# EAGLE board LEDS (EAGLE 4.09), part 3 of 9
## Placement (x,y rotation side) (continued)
LED19.97  LED_CROSS1/2  [LED_603]  60.1,4.28 180 top
LED19.98  LED_CROSS1/2  [LED_603]  61.89,4.28 180 top
LED19.99  LED_CROSS1/2  [LED_603]  63.68,4.28 180 top
LED19.100  LED_CROSS1/2  [LED_603]  65.49,4.28 180 top
LED19.101  LED_CROSS1/2  [LED_603]  67.18,4.32 180 top
LED19.102  LED_CROSS1/2  [LED_603]  68.95,4.32 180 top
LED19.103  LED_CROSS1/2  [LED_603]  70.7,4.32 180 top
LED19.104  LED_CROSS1/2  [LED_603]  72.45,4.32 180 top
LED19.105  LED_CROSS1/2  [LED_603]  74.2,4.32 180 top
LED19.106  LED_CROSS1/2  [LED_603]  75.95,4.32 180 top
LED19.107  LED_CROSS1/2  [LED_603]  77.73,4.32 180 top
LED19.108  LED_CROSS1/2  [LED_603]  79.48,4.32 180 top
LED19.109  LED_CROSS1/2  [LED_603]  81.23,4.32 180 top
LED19.110  LED_CROSS1/2  [LED_603]  83.21,4.32 180 top
LED19.111  LED_CROSS1/2  [LED_603]  85.11,4.32 180 top
LED19.112  LED_CROSS1/2  [LED_603]  86.78,4.32 180 top
LED19.113  LED_CROSS1/2  [LED_603]  88.65,4.32 180 top
LED19.114  LED_CROSS1/2  [LED_603]  90.28,4.32 180 top
LED19.115  LED_CROSS1/2  [LED_603]  92,4.32 180 top
LED19.116  LED_CROSS1/2  [LED_603]  93.8,4.32 180 top
LED19.117  LED_CROSS1/2  [LED_603]  95.45,4.32 180 top
LED19.118  LED_CROSS1/2  [LED_603]  97.25,4.32 180 top
LED19.119  LED_CROSS1/2  [LED_603]  99,4.32 180 top
LED19.120  LED_CROSS1/2  [LED_603]  100.73,4.32 180 top
LED19.121  LED_CROSS1/2  [LED_603]  102.5,4.32 180 top
LED19.122  LED_CROSS1/2  [LED_603]  104.2,4.32 180 top
LED19.123  LED_CROSS1/2  [LED_603]  106,4.32 180 top
LED19.124  LED_CROSS1/2  [LED_603]  107.68,4.32 180 top
LED19.125  LED_CROSS1/2  [LED_603]  109.3,4.32 180 top
LED19.126  LED_CROSS1/2  [LED_603]  111.23,4.32 180 top
LED19.127  LED_CROSS1/2  [LED_603]  112.8,4.32 180 top
LED20.0  LED_CROSS1/2  [LED_603]  2.57,30.59 180 top
LED20.1  LED_CROSS1/2  [LED_603]  4.37,30.59 180 top
LED20.2  LED_CROSS1/2  [LED_603]  6.18,30.59 180 top
LED20.3  LED_CROSS1/2  [LED_603]  7.97,30.59 180 top
LED20.4  LED_CROSS1/2  [LED_603]  9.73,30.59 180 top
LED20.5  LED_CROSS1/2  [LED_603]  11.52,30.59 180 top
LED20.6  LED_CROSS1/2  [LED_603]  13.32,30.59 180 top
LED20.7  LED_CROSS1/2  [LED_603]  15.12,30.59 180 top
LED20.8  LED_CROSS1/2  [LED_603]  16.92,30.59 180 top
LED20.9  LED_CROSS1/2  [LED_603]  18.72,30.59 180 top
LED20.10  LED_CROSS1/2  [LED_603]  20.52,30.59 180 top
LED20.11  LED_CROSS1/2  [LED_603]  22.32,30.59 180 top
LED20.12  LED_CROSS1/2  [LED_603]  24.11,30.59 180 top
LED20.13  LED_CROSS1/2  [LED_603]  25.92,30.59 180 top
LED20.14  LED_CROSS1/2  [LED_603]  27.72,30.59 180 top
LED20.15  LED_CROSS1/2  [LED_603]  29.52,30.59 180 top
LED20.16  LED_CROSS1/2  [LED_603]  31.32,30.59 180 top
LED20.17  LED_CROSS1/2  [LED_603]  33.11,30.59 180 top
LED20.18  LED_CROSS1/2  [LED_603]  34.93,30.59 180 top
LED20.19  LED_CROSS1/2  [LED_603]  36.72,30.59 180 top
LED20.20  LED_CROSS1/2  [LED_603]  38.51,30.59 180 top
LED20.21  LED_CROSS1/2  [LED_603]  40.33,30.59 180 top
LED20.22  LED_CROSS1/2  [LED_603]  42.12,30.59 180 top
LED20.23  LED_CROSS1/2  [LED_603]  43.92,30.59 180 top
LED20.24  LED_CROSS1/2  [LED_603]  45.71,30.59 180 top
LED20.25  LED_CROSS1/2  [LED_603]  47.51,30.59 180 top
LED20.26  LED_CROSS1/2  [LED_603]  49.3,30.59 180 top
LED20.27  LED_CROSS1/2  [LED_603]  51.12,30.59 180 top
LED20.28  LED_CROSS1/2  [LED_603]  52.91,30.59 180 top
LED20.29  LED_CROSS1/2  [LED_603]  54.71,30.59 180 top
LED20.30  LED_CROSS1/2  [LED_603]  56.5,30.59 180 top
LED20.31  LED_CROSS1/2  [LED_603]  58.3,30.59 180 top
LED20.33  LED_CROSS1/2  [LED_603]  60.1,30.59 180 top
LED20.34  LED_CROSS1/2  [LED_603]  61.89,30.59 180 top
LED20.35  LED_CROSS1/2  [LED_603]  63.68,30.59 180 top
LED20.36  LED_CROSS1/2  [LED_603]  65.47,30.59 180 top
LED20.37  LED_CROSS1/2  [LED_603]  67.38,30.59 180 top
LED20.38  LED_CROSS1/2  [LED_603]  69.16,30.59 180 top
LED20.39  LED_CROSS1/2  [LED_603]  70.91,30.59 180 top
LED20.40  LED_CROSS1/2  [LED_603]  72.66,30.59 180 top
LED20.41  LED_CROSS1/2  [LED_603]  74.41,30.59 180 top
LED20.42  LED_CROSS1/2  [LED_603]  76.16,30.59 180 top
LED20.43  LED_CROSS1/2  [LED_603]  77.91,30.59 180 top
LED20.44  LED_CROSS1/2  [LED_603]  79.66,30.59 180 top
LED20.45  LED_CROSS1/2  [LED_603]  81.43,30.59 180 top
LED20.46  LED_CROSS1/2  [LED_603]  83.18,30.59 180 top
LED20.47  LED_CROSS1/2  [LED_603]  84.93,30.59 180 top
LED20.48  LED_CROSS1/2  [LED_603]  86.68,30.59 180 top
LED20.49  LED_CROSS1/2  [LED_603]  88.43,30.59 180 top
LED20.50  LED_CROSS1/2  [LED_603]  90.18,30.59 180 top
LED20.51  LED_CROSS1/2  [LED_603]  91.95,30.59 180 top
LED20.52  LED_CROSS1/2  [LED_603]  93.7,30.59 180 top
LED20.53  LED_CROSS1/2  [LED_603]  95.45,30.59 180 top
LED20.54  LED_CROSS1/2  [LED_603]  97.2,30.59 180 top
LED20.55  LED_CROSS1/2  [LED_603]  98.95,30.59 180 top
LED20.56  LED_CROSS1/2  [LED_603]  100.68,30.59 180 top
LED20.57  LED_CROSS1/2  [LED_603]  102.41,30.59 180 top
LED20.58  LED_CROSS1/2  [LED_603]  104.16,30.59 180 top
LED20.59  LED_CROSS1/2  [LED_603]  105.91,30.59 180 top
LED20.60  LED_CROSS1/2  [LED_603]  107.66,30.59 180 top
LED20.61  LED_CROSS1/2  [LED_603]  109.41,30.59 180 top
LED20.62  LED_CROSS1/2  [LED_603]  111.16,30.59 180 top
LED20.63  LED_CROSS1/2  [LED_603]  112.91,30.59 180 top
LED20.64  LED_CROSS1/2  [LED_603]  2.57,1.74 180 top
LED20.65  LED_CROSS1/2  [LED_603]  4.36,1.74 180 top
LED20.66  LED_CROSS1/2  [LED_603]  6.18,1.74 180 top
LED20.67  LED_CROSS1/2  [LED_603]  7.96,1.74 180 top
LED20.68  LED_CROSS1/2  [LED_603]  9.72,1.74 180 top
LED20.69  LED_CROSS1/2  [LED_603]  11.52,1.74 180 top
LED20.70  LED_CROSS1/2  [LED_603]  13.32,1.74 180 top
LED20.71  LED_CROSS1/2  [LED_603]  14.88,1.74 180 top
LED20.72  LED_CROSS1/2  [LED_603]  16.93,1.74 180 top
LED20.73  LED_CROSS1/2  [LED_603]  18.72,1.74 180 top
LED20.74  LED_CROSS1/2  [LED_603]  20.52,1.74 180 top
LED20.75  LED_CROSS1/2  [LED_603]  22.31,1.74 180 top
LED20.76  LED_CROSS1/2  [LED_603]  24.12,1.74 180 top
LED20.77  LED_CROSS1/2  [LED_603]  25.92,1.74 180 top
LED20.78  LED_CROSS1/2  [LED_603]  27.72,1.74 180 top
LED20.79  LED_CROSS1/2  [LED_603]  29.52,1.74 180 top
LED20.80  LED_CROSS1/2  [LED_603]  31.31,1.74 180 top
LED20.81  LED_CROSS1/2  [LED_603]  33.13,1.74 180 top
LED20.82  LED_CROSS1/2  [LED_603]  34.92,1.74 180 top
LED20.83  LED_CROSS1/2  [LED_603]  36.72,1.74 180 top
LED20.84  LED_CROSS1/2  [LED_603]  38.53,1.72 180 top
LED20.85  LED_CROSS1/2  [LED_603]  40.32,1.72 180 top
LED20.86  LED_CROSS1/2  [LED_603]  42.12,1.72 180 top
LED20.87  LED_CROSS1/2  [LED_603]  43.92,1.72 180 top
LED20.88  LED_CROSS1/2  [LED_603]  45.71,1.72 180 top
LED20.89  LED_CROSS1/2  [LED_603]  47.51,1.72 180 top
LED20.90  LED_CROSS1/2  [LED_603]  49.3,1.72 180 top
LED20.91  LED_CROSS1/2  [LED_603]  51.1,1.72 180 top
LED20.92  LED_CROSS1/2  [LED_603]  52.91,1.72 180 top
LED20.93  LED_CROSS1/2  [LED_603]  54.71,1.72 180 top
LED20.94  LED_CROSS1/2  [LED_603]  56.51,1.72 180 top
LED20.96  LED_CROSS1/2  [LED_603]  58.3,1.72 180 top
LED20.97  LED_CROSS1/2  [LED_603]  60.1,1.7 180 top
LED20.98  LED_CROSS1/2  [LED_603]  61.89,1.7 180 top
LED20.99  LED_CROSS1/2  [LED_603]  63.7,1.7 180 top
LED20.100  LED_CROSS1/2  [LED_603]  65.49,1.7 180 top
LED20.101  LED_CROSS1/2  [LED_603]  67.16,1.74 180 top
LED20.102  LED_CROSS1/2  [LED_603]  68.95,1.74 180 top
LED20.103  LED_CROSS1/2  [LED_603]  70.7,1.74 180 top
LED20.104  LED_CROSS1/2  [LED_603]  72.45,1.74 180 top
LED20.105  LED_CROSS1/2  [LED_603]  74.2,1.74 180 top
LED20.106  LED_CROSS1/2  [LED_603]  75.95,1.74 180 top
LED20.107  LED_CROSS1/2  [LED_603]  77.7,1.74 180 top
LED20.108  LED_CROSS1/2  [LED_603]  79.45,1.74 180 top
LED20.109  LED_CROSS1/2  [LED_603]  81.23,1.74 180 top
LED20.110  LED_CROSS1/2  [LED_603]  83.15,1.74 180 top
LED20.111  LED_CROSS1/2  [LED_603]  84.98,1.74 180 top
LED20.112  LED_CROSS1/2  [LED_603]  86.78,1.74 180 top
LED20.113  LED_CROSS1/2  [LED_603]  88.55,1.74 180 top
LED20.114  LED_CROSS1/2  [LED_603]  90.28,1.74 180 top
LED20.115  LED_CROSS1/2  [LED_603]  92,1.74 180 top
LED20.116  LED_CROSS1/2  [LED_603]  93.8,1.74 180 top
LED20.117  LED_CROSS1/2  [LED_603]  95.45,1.74 180 top
LED20.118  LED_CROSS1/2  [LED_603]  97.3,1.74 180 top
LED20.119  LED_CROSS1/2  [LED_603]  99,1.74 180 top
LED20.120  LED_CROSS1/2  [LED_603]  100.73,1.74 180 top
LED20.121  LED_CROSS1/2  [LED_603]  102.55,1.74 180 top
LED20.122  LED_CROSS1/2  [LED_603]  104.2,1.74 180 top
LED20.123  LED_CROSS1/2  [LED_603]  106,1.74 180 top
LED20.124  LED_CROSS1/2  [LED_603]  107.6,1.74 180 top
LED20.125  LED_CROSS1/2  [LED_603]  109.3,1.74 180 top
LED20.126  LED_CROSS1/2  [LED_603]  111.25,1.74 180 top
LED20.127  LED_CROSS1/2  [LED_603]  112.8,1.74 180 top
LED21.0  [LED_603]  2.57,27.87 180 top
LED21.1  [LED_603]  4.37,27.87 180 top
LED21.2  [LED_603]  6.18,27.87 180 top
LED21.3  [LED_603]  7.98,27.87 180 top
LED21.4  [LED_603]  9.73,27.87 180 top
LED21.5  [LED_603]  11.52,27.87 180 top
LED21.6  [LED_603]  13.32,27.87 180 top
LED21.7  [LED_603]  15.12,27.87 180 top
LED21.8  [LED_603]  16.92,27.87 180 top
LED21.9  [LED_603]  18.72,27.87 180 top
LED21.10  [LED_603]  20.52,27.87 180 top
LED21.11  [LED_603]  22.32,27.87 180 top
LED21.12  [LED_603]  24.11,27.87 180 top
LED21.13  [LED_603]  25.92,27.87 180 top
LED21.14  [LED_603]  27.72,27.87 180 top
LED21.15  [LED_603]  29.52,27.87 180 top
LED21.16  [LED_603]  31.32,27.87 180 top
LED21.17  [LED_603]  33.11,27.87 180 top
LED21.18  [LED_603]  34.93,27.89 180 top
LED21.19  [LED_603]  36.72,27.87 180 top
LED21.20  [LED_603]  38.51,27.87 180 top
LED21.21  [LED_603]  40.33,27.86 180 top
LED21.22  [LED_603]  42.12,27.87 180 top
LED21.23  [LED_603]  43.92,27.87 180 top
LED21.24  [LED_603]  45.71,27.87 180 top
LED21.25  [LED_603]  47.51,27.87 180 top
LED21.26  [LED_603]  49.28,27.87 180 top
LED21.27  [LED_603]  51.12,27.87 180 top
LED21.28  [LED_603]  52.94,27.87 180 top
LED21.29  [LED_603]  54.71,27.87 180 top
LED21.30  [LED_603]  56.5,27.87 180 top
LED21.31  [LED_603]  58.3,27.87 180 top
LED21.33  [LED_603]  60.1,27.87 180 top
LED21.34  [LED_603]  61.89,27.85 180 top
LED21.35  [LED_603]  63.68,27.87 180 top
LED21.36  [LED_603]  65.49,27.85 180 top
LED21.37  [LED_603]  67.38,27.87 180 top
LED21.38  [LED_603]  69.16,27.87 180 top
LED21.39  [LED_603]  70.91,27.87 180 top
LED21.40  [LED_603]  72.66,27.87 180 top
LED21.41  [LED_603]  74.41,27.87 180 top
LED21.42  [LED_603]  76.16,27.87 180 top
LED21.43  [LED_603]  77.91,27.87 180 top
LED21.44  [LED_603]  79.66,27.87 180 top
LED21.45  [LED_603]  81.43,27.87 180 top
LED21.46  [LED_603]  83.18,27.87 180 top
LED21.47  [LED_603]  84.93,27.87 180 top
LED21.48  [LED_603]  86.68,27.87 180 top
LED21.49  [LED_603]  88.43,27.87 180 top
LED21.50  [LED_603]  90.18,27.87 180 top
LED21.51  [LED_603]  91.95,27.87 180 top
LED21.52  [LED_603]  93.7,27.87 180 top
LED21.53  [LED_603]  95.45,27.87 180 top
LED21.54  [LED_603]  97.2,27.87 180 top
LED21.55  [LED_603]  98.95,27.87 180 top
LED21.56  [LED_603]  100.68,27.87 180 top
LED21.57  [LED_603]  102.41,27.87 180 top
LED21.58  [LED_603]  104.16,27.87 180 top
LED21.59  [LED_603]  105.91,27.87 180 top
LED21.60  [LED_603]  107.66,27.87 180 top
LED21.61  [LED_603]  109.41,27.87 180 top
LED21.62  [LED_603]  111.16,27.87 180 top
LED21.63  [LED_603]  112.91,27.87 180 top
X0  PAD_PIN  [PAD0.012]  3.51,84.97 0 top
X1  PAD_PIN  [PAD0.012]  5.31,84.97 0 top
X2  PAD_PIN  [PAD0.012]  7.16,84.97 0 top
X3  PAD_PIN  [PAD0.012]  8.86,84.97 0 top
X4  PAD_PIN  [PAD0.012]  10.69,84.97 0 top
X5  PAD_PIN  [PAD0.012]  12.39,84.97 0 top
X6  PAD_PIN  [PAD0.012]  14.09,84.97 0 top
X7  PAD_PIN  [PAD0.012]  15.96,84.97 0 top
X8  PAD_PIN  [PAD0.012]  17.71,84.97 0 top
X9  PAD_PIN  [PAD0.012]  19.49,84.97 0 top
X10  PAD_PIN  [PAD0.012]  21.31,84.97 0 top
X11  PAD_PIN  [PAD0.012]  22.98,84.97 0 top
X12  PAD_PIN  [PAD0.012]  24.76,84.97 0 top
X13  PAD_PIN  [PAD0.012]  26.46,84.97 0 top
X14  PAD_PIN  [PAD0.012]  28.24,84.97 0 top
X15  PAD_PIN  [PAD0.012]  29.99,84.97 0 top
X16  PAD_PIN  [PAD0.012]  31.73,84.97 0 top
X17  PAD_PIN  [PAD0.012]  33.46,84.97 0 top
X18  PAD_PIN  [PAD0.012]  35.76,84.97 0 top
X19  PAD_PIN  [PAD0.012]  37.59,84.97 0 top
X20  PAD_PIN  [PAD0.012]  39.51,84.97 0 top
X22  PAD_PIN  [PAD0.012]  41.23,84.97 0 top
X23  PAD_PIN  [PAD0.012]  42.98,84.97 0 top
X24  PAD_PIN  [PAD0.012]  44.7,84.97 0 top
X25  PAD_PIN  [PAD0.012]  46.66,84.97 0 top
X26  PAD_PIN  [PAD0.012]  48.41,84.97 0 top
X27  PAD_PIN  [PAD0.012]  50.19,84.97 0 top
X28  PAD_PIN  [PAD0.012]  52.04,84.97 0 top
X29  PAD_PIN  [PAD0.012]  53.8,84.97 0 top
X30  PAD_PIN  [PAD0.012]  55.5,84.97 0 top
X31  PAD_PIN  [PAD0.012]  57.38,84.97 0 top
X32  PAD_PIN  [PAD0.012]  59.3,84.97 0 top
X33  PAD_PIN  [PAD0.012]  61,84.97 0 top
X34  PAD_PIN  [PAD0.012]  62.78,84.97 0 top
X35  PAD_PIN  [PAD0.012]  64.61,84.97 0 top
X36  PAD_PIN  [PAD0.012]  66.5,84.97 0 top
X37  PAD_PIN  [PAD0.012]  68.03,84.97 0 top
X38  PAD_PIN  [PAD0.012]  70.16,84.97 0 top
X39  PAD_PIN  [PAD0.012]  71.56,84.97 0 top
X40  PAD_PIN  [PAD0.012]  73.56,84.97 0 top
X41  PAD_PIN  [PAD0.012]  75.39,84.97 0 top
X42  PAD_PIN  [PAD0.012]  77.21,84.97 0 top
X43  PAD_PIN  [PAD0.012]  78.71,84.97 0 top
X44  PAD_PIN  [PAD0.012]  80.61,84.97 0 top
X45  PAD_PIN  [PAD0.012]  82.19,84.97 0 top
X46  PAD_PIN  [PAD0.012]  84.19,84.97 0 top
X47  PAD_PIN  [PAD0.012]  85.91,84.97 0 top
X48  PAD_PIN  [PAD0.012]  87.59,84.97 0 top
X49  PAD_PIN  [PAD0.012]  89.41,84.97 0 top
X50  PAD_PIN  [PAD0.012]  91.14,84.97 0 top
X51  PAD_PIN  [PAD0.012]  92.94,84.97 0 top
X52  PAD_PIN  [PAD0.012]  94.69,84.97 0 top
X53  PAD_PIN  [PAD0.012]  96.39,84.97 0 top
X54  PAD_PIN  [PAD0.012]  98.19,84.97 0 top
X55  PAD_PIN  [PAD0.012]  99.84,84.97 0 top
X56  PAD_PIN  [PAD0.012]  101.66,84.97 0 top
X57  PAD_PIN  [PAD0.012]  103.48,84.97 0 top
X58  PAD_PIN  [PAD0.012]  105.19,84.97 0 top
X59  PAD_PIN  [PAD0.012]  106.91,84.97 0 top
X60  PAD_PIN  [PAD0.012]  108.61,84.97 0 top
X61  PAD_PIN  [PAD0.012]  110.31,84.97 0 top
X62  PAD_PIN  [PAD0.012]  112.14,84.97 0 top
X63  PAD_PIN  [PAD0.012]  113.81,84.96 0 top
Y.0  PAD_PIN  [PAD0.012]  0.97,81.98 0 top
Y.1  PAD_PIN  [PAD0.012]  1.02,79.38 0 top
Y.2  PAD_PIN  [PAD0.012]  0.99,76.81 0 top
Y.3  PAD_PIN  [PAD0.012]  1.02,74.23 0 top
Y.4  PAD_PIN  [PAD0.012]  1.02,71.71 90 top
Y.5  PAD_PIN  [PAD0.012]  1.07,69.11 0 top
Y.6  PAD_PIN  [PAD0.012]  1.02,66.48 0 top
Y.7  PAD_PIN  [PAD0.012]  1.02,63.86 0 top
Y.8  PAD_PIN  [PAD0.012]  1.04,61.21 0 top
Y.9  PAD_PIN  [PAD0.012]  1.07,58.66 0 top
Y.10  [PAD0.012]  1.07,55.94 0 top
Y.11  PAD_PIN  [PAD0.012]  1.08,53.22 0 top
Y.12  PAD_PIN  [PAD0.012]  1.08,50.62 0 top
Y.13  PAD_PIN  [PAD0.012]  1.08,48.04 0 top
Y.14  PAD_PIN  [PAD0.012]  1.08,45.47 0 top
Y.15  PAD_PIN  [PAD0.012]  1.25,42.94 90 top
Y.16  PAD_PIN  [PAD0.012]  1.3,40.34 0 top
Y.17  PAD_PIN  [PAD0.012]  1.25,37.72 0 top
Y.18  PAD_PIN  [PAD0.012]  1.13,35.09 0 top
Y.19  PAD_PIN  [PAD0.012]  1.27,32.32 0 top
Y.20  PAD_PIN  [PAD0.012]  1.18,29.89 0 top
Y.21  [PAD0.012]  1.18,27.17 0 top
Y.22  PAD_PIN  [PAD0.012]  1.17,24.37 0 top
Y.23  PAD_PIN  [PAD0.012]  1.13,21.77 0 top
Y.24  PAD_PIN  [PAD0.012]  1.14,19.06 0 top
Y.25  PAD_PIN  [PAD0.012]  1.25,16.62 0 top
Y.26  PAD_PIN  [PAD0.012]  1.24,14.09 90 top
Y.27  PAD_PIN  [PAD0.012]  1.26,11.49 0 top
Y.28  PAD_PIN  [PAD0.012]  1.05,8.87 0 top
Y.29  PAD_PIN  [PAD0.012]  1.05,6.24 0 top
Y.30  PAD_PIN  [PAD0.012]  1.07,3.59 0 top
Y.31  PAD_PIN  [PAD0.012]  1.1,1.04 0 top

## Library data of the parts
E$1 X0 X1-X20 X22-X63 Y.0 Y.1-Y.31 = Devs
LED0.0 LED0.1-LED0.35 LED0.37-LED0.62 LED1.0 LED1.1-LED1.66 LED2.0 LED2.1-LED2.82 LED3.0 LED3.1-LED3.35 LED3.37-LED3.63 LED4.0 LED4.1-LED4.35 LED4.37-LED4.63 LED5.0 LED5.1-LED5.29 LED5.31-LED5.63 LED6.0 LED6.1-LED6.31 LED6.33-LED6.63 LED7.0 LED7.1-LED7.31 LED7.33-LED7.63 LED8.0 LED8.1-LED8.31 LED8.33-LED8.63 LED9.0 LED9.1-LED9.31 LED9.33-LED9.63 LED10.0 LED10.1-LED10.31 LED10.33-LED10.63 LED11.0 LED11.1-LED11.31 LED11.33-LED11.127 LED12.0 LED12.1-LED12.31 LED12.33-LED12.95 LED12.98-LED12.127 LED13.0 LED13.1-LED13.32 LED13.34-LED13.127 LED14.0 LED14.1-LED14.133 LED15.0 LED15.1-LED15.32 LED15.34-LED15.95 LED15.97-LED15.127 LED16.0 LED16.1-LED16.31 LED16.33-LED16.95 LED16.97-LED16.127 LED17.0 LED17.1-LED17.31 LED17.33-LED17.95 LED17.97-LED17.127 LED18.0 LED18.1-LED18.31 LED18.33-LED18.96 LED18.98-LED18.127 LED19.0 LED19.1-LED19.31 LED19.33-LED19.94 LED19.96-LED19.127 LED20.0 LED20.1-LED20.31 LED20.33-LED20.94 LED20.96-LED20.127 LED21.0 LED21.1-LED21.31 LED21.33-LED21.63 = miniled

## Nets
LED2.27: LED11.91.P$A LED12.91.P$A LED13.27.P$A LED13.91.P$A LED14.27.P$A LED14.91.P$A LED15.27.P$A LED15.91.P$A LED16.27.P$A LED16.91.P$A LED17.27.P$A LED17.91.P$A LED18.27.P$A LED18.91.P$A LED19.27.P$A LED19.91.P$A LED20.27.P$A LED20.91.P$A LED21.27.P$A
N$X.0: LED0.0.P$A LED1.0.P$A LED2.0.P$A LED3.0.P$A LED4.0.P$A LED5.0.P$A LED6.0.P$A LED7.0.P$A LED8.0.P$A LED9.0.P$A LED10.0.P$A LED11.0.P$A LED11.64.P$A LED12.0.P$A LED12.64.P$A LED13.0.P$A LED13.64.P$A LED14.0.P$A LED14.64.P$A LED15.0.P$A LED15.64.P$A LED16.0.P$A LED16.64.P$A LED17.0.P$A LED17.64.P$A LED18.0.P$A LED18.64.P$A LED19.0.P$A LED19.64.P$A LED20.0.P$A LED20.64.P$A LED21.0.P$A X0.P$
N$X.1: LED5.1.P$A LED6.1.P$A LED7.1.P$A LED8.1.P$A LED9.1.P$A LED10.1.P$A LED11.1.P$A LED11.65.P$A LED12.1.P$A LED12.65.P$A LED13.1.P$A LED13.65.P$A LED14.1.P$A LED14.65.P$A LED15.1.P$A LED15.65.P$A LED16.1.P$A LED16.65.P$A LED17.1.P$A LED17.65.P$A LED18.1.P$A LED18.65.P$A LED19.1.P$A LED19.65.P$A LED20.1.P$A LED20.65.P$A LED21.1.P$A
N$X.2: LED1.2.P$A LED2.2.P$A LED3.2.P$A LED4.2.P$A LED5.2.P$A LED6.2.P$A LED7.2.P$A LED8.2.P$A LED9.2.P$A LED10.2.P$A LED11.2.P$A LED11.66.P$A LED12.2.P$A LED12.66.P$A LED13.2.P$A LED13.66.P$A LED14.2.P$A LED14.66.P$A LED15.2.P$A LED15.66.P$A LED16.2.P$A LED16.66.P$A LED17.2.P$A LED17.66.P$A LED18.2.P$A LED18.66.P$A LED19.2.P$A LED19.66.P$A LED20.2.P$A LED20.66.P$A LED21.2.P$A
N$X.3: LED0.3.P$A LED1.3.P$A LED2.3.P$A LED3.3.P$A LED4.3.P$A LED5.3.P$A LED6.3.P$A LED7.3.P$A LED8.3.P$A LED9.3.P$A LED10.3.P$A LED11.3.P$A LED11.67.P$A LED12.3.P$A LED12.67.P$A LED13.3.P$A LED13.67.P$A LED14.3.P$A LED14.67.P$A LED15.3.P$A LED15.67.P$A LED16.3.P$A LED16.67.P$A LED17.3.P$A LED17.67.P$A LED18.3.P$A LED18.67.P$A LED19.3.P$A LED19.67.P$A LED20.3.P$A LED20.67.P$A LED21.3.P$A X3.P$
N$X.4: LED0.4.P$A LED1.4.P$A LED2.4.P$A LED3.4.P$A LED4.4.P$A LED5.4.P$A LED6.4.P$A LED7.4.P$A LED8.4.P$A LED9.4.P$A LED10.4.P$A LED11.4.P$A LED11.68.P$A LED12.4.P$A LED12.68.P$A LED13.4.P$A LED13.68.P$A LED14.4.P$A LED14.68.P$A LED15.4.P$A LED15.68.P$A LED16.4.P$A LED16.68.P$A LED17.4.P$A LED17.68.P$A LED18.4.P$A LED18.68.P$A LED19.4.P$A LED19.68.P$A LED20.4.P$A LED20.68.P$A LED21.4.P$A X4.P$
N$X.5: LED0.5.P$A LED1.5.P$A LED2.5.P$A LED3.5.P$A LED4.5.P$A LED5.5.P$A LED6.5.P$A LED7.5.P$A LED8.5.P$A LED9.5.P$A LED10.5.P$A LED11.5.P$A LED11.69.P$A LED12.5.P$A LED12.69.P$A LED13.5.P$A LED13.69.P$A LED14.5.P$A LED14.69.P$A LED15.5.P$A LED15.69.P$A LED16.5.P$A LED16.69.P$A LED17.5.P$A LED17.69.P$A LED18.5.P$A LED18.69.P$A LED19.5.P$A LED19.69.P$A LED20.5.P$A LED20.69.P$A LED21.5.P$A X5.P$
N$X.6: LED0.6.P$A LED1.6.P$A LED2.6.P$A LED3.6.P$A LED4.6.P$A LED5.6.P$A LED6.6.P$A LED7.6.P$A LED8.6.P$A LED9.6.P$A LED10.6.P$A LED11.6.P$A LED11.70.P$A LED12.6.P$A LED12.70.P$A LED13.6.P$A LED13.70.P$A LED14.6.P$A LED14.70.P$A LED15.6.P$A LED15.70.P$A LED16.6.P$A LED16.70.P$A LED17.6.P$A LED17.70.P$A LED18.6.P$A LED18.70.P$A LED19.6.P$A LED19.70.P$A LED20.6.P$A LED20.70.P$A LED21.6.P$A X6.P$
N$X.7: LED1.7.P$A LED2.7.P$A LED3.7.P$A LED4.7.P$A LED5.7.P$A LED6.7.P$A LED7.7.P$A LED8.7.P$A LED9.7.P$A LED10.7.P$A LED11.7.P$A LED11.71.P$A LED12.7.P$A LED12.71.P$A LED13.7.P$A LED13.71.P$A LED14.7.P$A LED14.71.P$A LED15.7.P$A LED15.71.P$A LED16.7.P$A LED16.71.P$A LED17.7.P$A LED17.71.P$A LED18.7.P$A LED18.71.P$A LED19.7.P$A LED19.71.P$A LED20.7.P$A LED20.71.P$A LED21.7.P$A
N$X.8: LED0.8.P$A LED1.8.P$A LED2.8.P$A LED3.8.P$A LED4.8.P$A LED5.8.P$A LED6.8.P$A LED7.8.P$A LED8.8.P$A LED9.8.P$A LED10.8.P$A LED11.8.P$A LED11.72.P$A LED12.8.P$A LED12.72.P$A LED13.8.P$A LED13.72.P$A LED14.8.P$A LED14.72.P$A LED15.8.P$A LED15.72.P$A LED16.8.P$A LED16.72.P$A LED17.8.P$A LED17.72.P$A LED18.8.P$A LED18.72.P$A LED19.8.P$A LED19.72.P$A LED20.8.P$A LED20.72.P$A LED21.8.P$A X8.P$
N$X.9: LED1.9.P$A LED2.9.P$A LED3.9.P$A LED4.9.P$A LED5.9.P$A LED6.9.P$A LED7.9.P$A LED8.9.P$A LED9.9.P$A LED10.9.P$A LED11.9.P$A LED11.73.P$A LED12.9.P$A LED12.73.P$A LED13.9.P$A LED13.73.P$A LED14.9.P$A LED14.73.P$A LED15.9.P$A LED15.73.P$A LED16.9.P$A LED16.73.P$A LED17.9.P$A LED17.73.P$A LED18.9.P$A LED18.73.P$A LED19.9.P$A LED19.73.P$A LED20.9.P$A LED20.73.P$A LED21.9.P$A
N$X.10: LED1.10.P$A LED2.10.P$A LED3.10.P$A LED4.10.P$A LED5.10.P$A LED6.10.P$A LED7.10.P$A LED8.10.P$A LED9.10.P$A LED10.10.P$A LED11.10.P$A LED11.74.P$A LED12.10.P$A LED12.74.P$A LED13.10.P$A LED13.74.P$A LED14.10.P$A LED14.74.P$A LED15.10.P$A LED15.74.P$A LED16.10.P$A LED16.74.P$A LED17.10.P$A LED17.74.P$A LED18.10.P$A LED18.74.P$A LED19.10.P$A LED19.74.P$A LED20.10.P$A LED20.74.P$A LED21.10.P$A
N$X.11: LED7.11.P$A LED8.11.P$A LED9.11.P$A LED10.11.P$A LED11.11.P$A LED11.75.P$A LED12.11.P$A LED12.75.P$A LED13.11.P$A LED13.75.P$A LED14.11.P$A LED14.75.P$A LED15.11.P$A LED15.75.P$A LED16.11.P$A LED16.75.P$A LED17.11.P$A LED17.75.P$A LED18.11.P$A LED18.75.P$A LED19.11.P$A LED19.75.P$A LED20.11.P$A LED20.75.P$A LED21.11.P$A
N$X.12: LED1.12.P$A LED2.12.P$A LED3.12.P$A LED4.12.P$A LED5.12.P$A LED6.12.P$A LED7.12.P$A LED8.12.P$A LED9.12.P$A LED10.12.P$A LED11.12.P$A LED11.76.P$A LED12.12.P$A LED12.76.P$A LED13.12.P$A LED13.76.P$A LED14.12.P$A LED14.76.P$A LED15.12.P$A LED15.76.P$A LED16.12.P$A LED16.76.P$A LED17.12.P$A LED17.76.P$A LED18.12.P$A LED18.76.P$A LED19.12.P$A LED19.76.P$A LED20.12.P$A LED20.76.P$A LED21.12.P$A
N$X.13: LED1.13.P$A LED2.13.P$A LED3.13.P$A LED4.13.P$A LED5.13.P$A LED6.13.P$A LED7.13.P$A LED8.13.P$A LED9.13.P$A LED10.13.P$A LED11.13.P$A LED11.77.P$A LED12.13.P$A LED12.77.P$A LED13.13.P$A LED13.77.P$A LED14.13.P$A LED14.77.P$A LED15.13.P$A LED15.77.P$A LED16.13.P$A LED16.77.P$A LED17.13.P$A LED17.77.P$A LED18.13.P$A LED18.77.P$A LED19.13.P$A LED19.77.P$A LED20.13.P$A LED20.77.P$A LED21.13.P$A
N$X.14: LED1.14.P$A LED2.14.P$A LED3.14.P$A LED4.14.P$A LED5.14.P$A LED6.14.P$A LED7.14.P$A LED8.14.P$A LED9.14.P$A LED10.14.P$A LED11.14.P$A LED11.78.P$A LED12.14.P$A LED12.78.P$A LED13.14.P$A LED13.78.P$A LED14.14.P$A LED14.78.P$A LED15.14.P$A LED15.78.P$A LED16.14.P$A LED16.78.P$A LED17.14.P$A LED17.78.P$A LED18.14.P$A LED18.78.P$A LED19.14.P$A LED19.78.P$A LED20.14.P$A LED20.78.P$A LED21.14.P$A
N$X.15: LED1.15.P$A LED2.15.P$A LED3.15.P$A LED4.15.P$A LED5.15.P$A LED6.15.P$A LED7.15.P$A LED8.15.P$A LED9.15.P$A LED10.15.P$A LED11.15.P$A LED11.79.P$A LED12.15.P$A LED12.79.P$A LED13.15.P$A LED13.79.P$A LED14.15.P$A LED14.79.P$A LED15.15.P$A LED15.79.P$A LED16.15.P$A LED16.79.P$A LED17.15.P$A LED17.79.P$A LED18.15.P$A LED18.79.P$A LED19.15.P$A LED19.79.P$A LED20.15.P$A LED20.79.P$A LED21.15.P$A
N$X.16: LED1.16.P$A LED2.16.P$A LED3.16.P$A LED4.16.P$A LED5.16.P$A LED6.16.P$A LED7.16.P$A LED8.16.P$A LED9.16.P$A LED10.16.P$A LED11.16.P$A LED11.80.P$A LED12.16.P$A LED12.80.P$A LED13.16.P$A LED13.80.P$A LED14.16.P$A LED14.80.P$A LED15.16.P$A LED15.80.P$A LED16.16.P$A LED16.80.P$A LED17.16.P$A LED17.80.P$A LED18.16.P$A LED18.80.P$A LED19.16.P$A LED19.80.P$A LED20.16.P$A LED20.80.P$A LED21.16.P$A
N$X.17: LED1.17.P$A LED2.17.P$A LED3.17.P$A LED4.17.P$A LED5.17.P$A LED6.17.P$A LED7.17.P$A LED8.17.P$A LED9.17.P$A LED10.17.P$A LED11.17.P$A LED11.81.P$A LED12.17.P$A LED12.81.P$A LED13.17.P$A LED13.81.P$A LED14.17.P$A LED14.81.P$A LED15.17.P$A LED15.81.P$A LED16.17.P$A LED16.81.P$A LED17.17.P$A LED17.81.P$A LED18.17.P$A LED18.81.P$A LED19.17.P$A LED19.81.P$A LED20.17.P$A LED20.81.P$A LED21.17.P$A
N$X.18: LED5.18.P$A LED6.18.P$A LED7.18.P$A LED8.18.P$A LED9.18.P$A LED10.18.P$A LED11.18.P$A LED11.82.P$A LED12.18.P$A LED12.82.P$A LED13.18.P$A LED13.82.P$A LED14.18.P$A LED14.82.P$A LED15.18.P$A LED15.82.P$A LED16.18.P$A LED16.82.P$A LED17.18.P$A LED17.82.P$A LED18.18.P$A LED18.82.P$A LED19.18.P$A LED19.82.P$A LED20.18.P$A LED20.82.P$A LED21.18.P$A
N$X.19: LED11.19.P$A LED11.83.P$A LED12.19.P$A LED12.83.P$A LED13.19.P$A LED13.83.P$A LED14.19.P$A LED14.83.P$A LED15.19.P$A LED15.83.P$A LED16.19.P$A LED16.83.P$A LED17.19.P$A LED17.83.P$A LED18.19.P$A LED18.83.P$A LED19.19.P$A LED19.83.P$A LED20.19.P$A LED20.83.P$A LED21.19.P$A
N$X.20: LED3.20.P$A LED4.20.P$A LED5.20.P$A LED6.20.P$A LED7.20.P$A LED8.20.P$A LED9.20.P$A LED10.20.P$A LED11.20.P$A LED11.84.P$A LED12.20.P$A LED12.84.P$A LED13.20.P$A LED13.84.P$A LED14.20.P$A LED14.84.P$A LED15.20.P$A LED15.84.P$A LED16.20.P$A LED16.84.P$A LED17.20.P$A LED17.84.P$A LED18.20.P$A LED18.84.P$A LED19.20.P$A LED19.84.P$A LED20.20.P$A LED20.84.P$A LED21.20.P$A
N$X.21: LED7.21.P$A LED8.21.P$A LED9.21.P$A LED10.21.P$A LED11.21.P$A LED11.85.P$A LED12.21.P$A LED12.85.P$A LED13.21.P$A LED13.85.P$A LED14.21.P$A LED14.85.P$A LED15.21.P$A LED15.85.P$A LED16.21.P$A LED16.85.P$A LED17.21.P$A LED17.85.P$A LED18.21.P$A LED18.85.P$A LED19.21.P$A LED19.85.P$A LED20.21.P$A LED20.85.P$A LED21.21.P$A
N$X.22: LED6.22.P$A LED7.22.P$A LED8.22.P$A LED9.22.P$A LED10.22.P$A LED11.22.P$A LED11.86.P$A LED12.22.P$A LED12.86.P$A LED13.22.P$A LED13.86.P$A LED14.22.P$A LED14.86.P$A LED15.22.P$A LED15.86.P$A LED16.22.P$A LED16.86.P$A LED17.22.P$A LED17.86.P$A LED18.22.P$A LED18.86.P$A LED19.22.P$A LED19.86.P$A LED20.22.P$A LED20.86.P$A LED21.22.P$A
N$X.23: LED10.23.P$A LED11.23.P$A LED11.87.P$A LED12.23.P$A LED12.87.P$A LED13.23.P$A LED13.87.P$A LED14.23.P$A LED14.87.P$A LED15.23.P$A LED15.87.P$A LED16.23.P$A LED16.87.P$A LED17.23.P$A LED17.87.P$A LED18.23.P$A LED18.87.P$A LED19.23.P$A LED19.87.P$A LED20.23.P$A LED20.87.P$A LED21.23.P$A
N$X.24: LED11.88.P$A LED12.24.P$A LED12.88.P$A LED13.24.P$A LED13.88.P$A LED14.24.P$A LED14.88.P$A LED15.24.P$A LED15.88.P$A LED16.24.P$A LED16.88.P$A LED17.24.P$A LED17.88.P$A LED18.24.P$A LED18.88.P$A LED19.24.P$A LED19.88.P$A LED20.24.P$A LED20.88.P$A LED21.24.P$A
N$X.25: LED7.25.P$A LED8.25.P$A LED9.25.P$A LED10.25.P$A LED11.25.P$A LED11.89.P$A LED12.25.P$A LED12.89.P$A LED13.25.P$A LED13.89.P$A LED14.25.P$A LED14.89.P$A LED15.25.P$A LED15.89.P$A LED16.25.P$A LED16.89.P$A LED17.25.P$A LED17.89.P$A LED18.25.P$A LED18.89.P$A LED19.25.P$A LED19.89.P$A LED20.25.P$A LED20.89.P$A LED21.25.P$A
N$X.26: LED7.26.P$A LED8.26.P$A LED9.26.P$A LED10.26.P$A LED11.26.P$A LED11.90.P$A LED12.26.P$A LED12.90.P$A LED13.26.P$A LED13.90.P$A LED14.26.P$A LED14.90.P$A LED15.26.P$A LED15.90.P$A LED16.26.P$A LED16.90.P$A LED17.26.P$A LED17.90.P$A LED18.26.P$A LED18.90.P$A LED19.26.P$A LED19.90.P$A LED20.26.P$A LED20.90.P$A LED21.26.P$A
N$X.28: LED6.28.P$A LED7.28.P$A LED8.28.P$A LED9.28.P$A LED10.28.P$A LED11.28.P$A LED11.92.P$A LED12.28.P$A LED12.92.P$A LED13.28.P$A LED13.92.P$A LED14.28.P$A LED14.92.P$A LED15.28.P$A LED15.92.P$A LED16.28.P$A LED16.92.P$A LED17.28.P$A LED17.92.P$A LED18.28.P$A LED18.92.P$A LED19.28.P$A LED19.92.P$A LED20.28.P$A LED20.92.P$A LED21.28.P$A
N$X.29: LED3.29.P$A LED4.29.P$A LED5.29.P$A LED6.29.P$A LED7.29.P$A LED8.29.P$A LED9.29.P$A LED10.29.P$A LED11.29.P$A LED11.93.P$A LED12.29.P$A LED12.93.P$A LED13.29.P$A LED13.93.P$A LED14.29.P$A LED14.93.P$A LED15.29.P$A LED15.93.P$A LED16.29.P$A LED16.93.P$A LED17.29.P$A LED17.93.P$A LED18.29.P$A LED18.93.P$A LED19.29.P$A LED19.93.P$A LED20.29.P$A LED20.93.P$A LED21.29.P$A
N$X.30: LED11.94.P$A LED12.94.P$A LED13.94.P$A LED14.94.P$A LED15.94.P$A LED16.94.P$A LED17.30.P$A LED17.94.P$A LED18.30.P$A LED18.94.P$A LED19.30.P$A LED19.94.P$A LED20.30.P$A LED20.94.P$A LED21.30.P$A
N$X.31: LED7.31.P$A LED8.31.P$A LED9.31.P$A LED10.31.P$A LED11.31.P$A LED11.95.P$A LED12.31.P$A LED12.95.P$A LED13.31.P$A LED13.95.P$A LED14.31.P$A LED14.95.P$A LED15.31.P$A LED15.95.P$A LED16.31.P$A LED16.95.P$A LED17.31.P$A LED17.95.P$A LED18.31.P$A LED18.95.P$A LED19.31.P$A LED20.31.P$A LED21.31.P$A
N$X.32: LED11.96.P$A LED13.32.P$A LED13.96.P$A LED14.32.P$A LED15.32.P$A LED18.96.P$A LED19.96.P$A LED20.96.P$A
N$X.33: LED7.33.P$A LED8.33.P$A LED9.33.P$A LED10.33.P$A LED11.33.P$A LED11.97.P$A LED12.33.P$A LED13.97.P$A LED14.33.P$A LED14.97.P$A LED15.97.P$A LED16.33.P$A LED16.97.P$A LED17.33.P$A LED17.97.P$A LED18.33.P$A LED19.33.P$A LED19.97.P$A LED20.33.P$A LED20.97.P$A LED21.33.P$A
N$X.34: LED7.34.P$A LED8.34.P$A LED9.34.P$A LED10.34.P$A LED11.34.P$A LED11.98.P$A LED12.34.P$A LED12.98.P$A LED13.34.P$A LED13.98.P$A LED14.34.P$A LED15.34.P$A LED15.98.P$A LED16.34.P$A LED16.98.P$A LED17.34.P$A LED17.98.P$A LED18.34.P$A LED18.98.P$A LED19.34.P$A LED19.98.P$A LED20.34.P$A LED20.98.P$A LED21.34.P$A
N$X.35: LED8.35.P$A LED9.35.P$A LED10.35.P$A LED11.35.P$A LED11.99.P$A LED12.35.P$A LED12.99.P$A LED13.35.P$A LED13.99.P$A LED14.35.P$A LED14.99.P$A LED15.35.P$A LED15.99.P$A LED16.35.P$A LED16.99.P$A LED17.35.P$A LED17.99.P$A LED18.35.P$A LED18.99.P$A LED19.35.P$A LED19.99.P$A LED20.35.P$A LED20.99.P$A LED21.35.P$A
N$X.36: LED7.36.P$A LED8.36.P$A LED9.36.P$A LED10.36.P$A LED11.36.P$A LED11.100.P$A LED12.36.P$A LED12.100.P$A LED13.36.P$A LED13.100.P$A LED14.36.P$A LED14.100.P$A LED15.36.P$A LED15.100.P$A LED16.36.P$A LED16.100.P$A LED17.36.P$A LED17.100.P$A LED18.36.P$A LED18.100.P$A LED19.36.P$A LED19.100.P$A LED20.36.P$A LED20.100.P$A LED21.36.P$A
N$X.37: LED6.37.P$A LED7.37.P$A LED8.37.P$A LED9.37.P$A LED10.37.P$A LED11.37.P$A LED11.101.P$A LED12.37.P$A LED12.101.P$A LED13.37.P$A LED13.101.P$A LED14.37.P$A LED14.101.P$A LED15.37.P$A LED15.101.P$A LED16.37.P$A LED16.101.P$A LED17.37.P$A LED17.101.P$A LED18.37.P$A LED18.101.P$A LED19.37.P$A LED19.101.P$A LED20.37.P$A LED20.101.P$A LED21.37.P$A
N$X.38: LED7.38.P$A LED8.38.P$A LED9.38.P$A LED10.38.P$A LED11.38.P$A LED11.102.P$A LED12.38.P$A LED12.102.P$A LED13.38.P$A LED13.102.P$A LED14.38.P$A LED14.102.P$A LED15.38.P$A LED15.102.P$A LED16.38.P$A LED16.102.P$A LED17.38.P$A LED17.102.P$A LED18.38.P$A LED18.102.P$A LED19.38.P$A LED19.102.P$A LED20.38.P$A LED20.102.P$A LED21.38.P$A
N$X.39: LED5.39.P$A LED6.39.P$A LED7.39.P$A LED8.39.P$A LED9.39.P$A LED10.39.P$A LED11.39.P$A LED11.103.P$A LED12.39.P$A LED12.103.P$A LED13.39.P$A LED13.103.P$A LED14.39.P$A LED14.103.P$A LED15.39.P$A LED15.103.P$A LED16.39.P$A LED16.103.P$A LED17.39.P$A LED17.103.P$A LED18.39.P$A LED18.103.P$A LED19.39.P$A LED19.103.P$A LED20.39.P$A LED20.103.P$A LED21.39.P$A
N$X.40: LED11.104.P$A LED12.104.P$A LED13.104.P$A LED14.104.P$A LED15.104.P$A LED16.104.P$A LED17.40.P$A LED17.104.P$A LED18.40.P$A LED18.104.P$A LED19.40.P$A LED19.104.P$A LED20.40.P$A LED20.104.P$A LED21.40.P$A
N$X.41: LED8.41.P$A LED9.41.P$A LED10.41.P$A LED11.41.P$A LED11.105.P$A LED12.41.P$A LED12.105.P$A LED13.41.P$A LED13.105.P$A LED14.41.P$A LED14.105.P$A LED15.41.P$A LED15.105.P$A LED16.41.P$A LED16.105.P$A LED17.41.P$A LED17.105.P$A LED18.41.P$A LED18.105.P$A LED19.41.P$A LED19.105.P$A LED20.41.P$A LED20.105.P$A LED21.41.P$A
N$X.42: LED9.42.P$A LED10.42.P$A LED11.42.P$A LED11.106.P$A LED12.42.P$A LED12.106.P$A LED13.42.P$A LED13.106.P$A LED14.42.P$A LED14.106.P$A LED15.42.P$A LED15.106.P$A LED16.42.P$A LED16.106.P$A LED17.42.P$A LED17.106.P$A LED18.42.P$A LED18.106.P$A LED19.42.P$A LED19.106.P$A LED20.42.P$A LED20.106.P$A LED21.42.P$A
N$X.43: LED11.107.P$A LED12.43.P$A LED12.107.P$A LED13.43.P$A LED13.107.P$A LED14.43.P$A LED14.107.P$A LED15.43.P$A LED15.107.P$A LED16.43.P$A LED16.107.P$A LED17.43.P$A LED17.107.P$A LED18.43.P$A LED18.107.P$A LED19.43.P$A LED19.107.P$A LED20.43.P$A LED20.107.P$A LED21.43.P$A
N$X.44: LED11.108.P$A LED12.108.P$A LED13.44.P$A LED13.108.P$A LED14.44.P$A LED14.108.P$A LED15.44.P$A LED15.108.P$A LED16.44.P$A LED16.108.P$A LED17.44.P$A LED17.108.P$A LED18.44.P$A LED18.108.P$A LED19.44.P$A LED19.108.P$A LED20.44.P$A LED20.108.P$A LED21.44.P$A
N$X.45: LED9.45.P$A LED10.45.P$A LED11.45.P$A LED11.109.P$A LED12.45.P$A LED12.109.P$A LED13.45.P$A LED13.109.P$A LED14.45.P$A LED14.109.P$A LED15.45.P$A LED15.109.P$A LED16.45.P$A LED16.109.P$A LED17.45.P$A LED17.109.P$A LED18.45.P$A LED18.109.P$A LED19.45.P$A LED19.109.P$A LED20.45.P$A LED20.109.P$A LED21.45.P$A
N$X.46: LED3.46.P$A LED4.46.P$A LED5.46.P$A LED6.46.P$A LED7.46.P$A LED8.46.P$A LED9.46.P$A LED10.46.P$A LED11.46.P$A LED11.110.P$A LED12.46.P$A LED12.110.P$A LED13.46.P$A LED13.110.P$A LED14.46.P$A LED14.110.P$A LED15.46.P$A LED15.110.P$A LED16.46.P$A LED16.110.P$A LED17.46.P$A LED17.110.P$A LED18.46.P$A LED18.110.P$A LED19.46.P$A LED19.110.P$A LED20.46.P$A LED20.110.P$A LED21.46.P$A
N$X.47: LED11.111.P$A LED12.47.P$A LED12.111.P$A LED13.47.P$A LED13.111.P$A LED14.47.P$A LED14.111.P$A LED15.47.P$A LED15.111.P$A LED16.47.P$A LED16.111.P$A LED17.47.P$A LED17.111.P$A LED18.47.P$A LED18.111.P$A LED19.47.P$A LED19.111.P$A LED20.47.P$A LED20.111.P$A LED21.47.P$A
N$X.48: LED11.112.P$A LED12.112.P$A LED13.112.P$A LED14.112.P$A LED15.112.P$A LED16.48.P$A LED16.112.P$A LED17.48.P$A LED17.112.P$A LED18.48.P$A LED18.112.P$A LED19.48.P$A LED19.112.P$A LED20.48.P$A LED20.112.P$A LED21.48.P$A
N$X.49: LED11.113.P$A LED12.49.P$A LED12.113.P$A LED13.49.P$A LED13.113.P$A LED14.49.P$A LED14.113.P$A LED15.49.P$A LED15.113.P$A LED16.49.P$A LED16.113.P$A LED17.49.P$A LED17.113.P$A LED18.49.P$A LED18.113.P$A LED19.49.P$A LED19.113.P$A LED20.49.P$A LED20.113.P$A LED21.49.P$A
N$X.50: LED3.50.P$A LED4.50.P$A LED5.50.P$A LED6.50.P$A LED7.50.P$A LED8.50.P$A LED9.50.P$A LED10.50.P$A LED11.50.P$A LED11.114.P$A LED12.50.P$A LED12.114.P$A LED13.50.P$A LED13.114.P$A LED14.50.P$A LED14.114.P$A LED15.50.P$A LED15.114.P$A LED16.50.P$A LED16.114.P$A LED17.50.P$A LED17.114.P$A LED18.50.P$A LED18.114.P$A LED19.50.P$A LED19.114.P$A LED20.50.P$A LED20.114.P$A LED21.50.P$A
N$X.51: LED11.115.P$A LED12.115.P$A LED13.115.P$A LED14.115.P$A LED15.51.P$A LED15.115.P$A LED16.51.P$A LED16.115.P$A LED17.51.P$A LED17.115.P$A LED18.51.P$A LED18.115.P$A LED19.51.P$A LED19.115.P$A LED20.51.P$A LED20.115.P$A LED21.51.P$A
N$X.52: LED10.52.P$A LED11.52.P$A LED11.116.P$A LED12.52.P$A LED12.116.P$A LED13.52.P$A LED13.116.P$A LED14.52.P$A LED14.116.P$A LED15.52.P$A LED15.116.P$A LED16.52.P$A LED16.116.P$A LED17.52.P$A LED17.116.P$A LED18.52.P$A LED18.116.P$A LED19.52.P$A LED19.116.P$A LED20.52.P$A LED20.116.P$A LED21.52.P$A
N$X.53: LED11.117.P$A LED12.53.P$A LED12.117.P$A LED13.53.P$A LED13.117.P$A LED14.53.P$A LED14.117.P$A LED15.53.P$A LED15.117.P$A LED16.53.P$A LED16.117.P$A LED17.53.P$A LED17.117.P$A LED18.53.P$A LED18.117.P$A LED19.53.P$A LED19.117.P$A LED20.53.P$A LED20.117.P$A LED21.53.P$A
N$X.54: LED6.54.P$A LED7.54.P$A LED8.54.P$A LED9.54.P$A LED10.54.P$A LED11.54.P$A LED11.118.P$A LED12.54.P$A LED12.118.P$A LED13.54.P$A LED13.118.P$A LED14.54.P$A LED14.118.P$A LED15.54.P$A LED15.118.P$A LED16.54.P$A LED16.118.P$A LED17.54.P$A LED17.118.P$A LED18.54.P$A LED18.118.P$A LED19.54.P$A LED19.118.P$A LED20.54.P$A LED20.118.P$A LED21.54.P$A
N$X.55: LED11.55.P$A LED11.119.P$A LED12.55.P$A LED12.119.P$A LED13.55.P$A LED13.119.P$A LED14.55.P$A LED14.119.P$A LED15.55.P$A LED15.119.P$A LED16.55.P$A LED16.119.P$A LED17.55.P$A LED17.119.P$A LED18.55.P$A LED18.119.P$A LED19.55.P$A LED19.119.P$A LED20.55.P$A LED20.119.P$A LED21.55.P$A
N$X.56: LED8.56.P$A LED9.56.P$A LED10.56.P$A LED11.56.P$A LED11.120.P$A LED12.56.P$A LED12.120.P$A LED13.56.P$A LED13.120.P$A LED14.56.P$A LED14.120.P$A LED15.56.P$A LED15.120.P$A LED16.56.P$A LED16.120.P$A LED17.56.P$A LED17.120.P$A LED18.56.P$A LED18.120.P$A LED19.56.P$A LED19.120.P$A LED20.56.P$A LED20.120.P$A LED21.56.P$A
N$X.57: LED8.57.P$A LED9.57.P$A LED10.57.P$A LED11.57.P$A LED11.121.P$A LED12.57.P$A LED12.121.P$A LED13.57.P$A LED13.121.P$A LED14.57.P$A LED14.121.P$A LED15.57.P$A LED15.121.P$A LED16.57.P$A LED16.121.P$A LED17.57.P$A LED17.121.P$A LED18.57.P$A LED18.121.P$A LED19.57.P$A LED19.121.P$A LED20.57.P$A LED20.121.P$A LED21.57.P$A
N$X.58: LED9.58.P$A LED10.58.P$A LED11.58.P$A LED11.122.P$A LED12.58.P$A LED12.122.P$A LED13.58.P$A LED13.122.P$A LED14.58.P$A LED14.122.P$A LED15.58.P$A LED15.122.P$A LED16.58.P$A LED16.122.P$A LED17.58.P$A LED17.122.P$A LED18.58.P$A LED18.122.P$A LED19.58.P$A LED19.122.P$A LED20.58.P$A LED20.122.P$A LED21.58.P$A
N$X.59: LED8.59.P$A LED9.59.P$A LED10.59.P$A LED11.59.P$A LED11.123.P$A LED12.59.P$A LED12.123.P$A LED13.59.P$A LED13.123.P$A LED14.59.P$A LED14.123.P$A LED15.59.P$A LED15.123.P$A LED16.59.P$A LED16.123.P$A LED17.59.P$A LED17.123.P$A LED18.59.P$A LED18.123.P$A LED19.59.P$A LED19.123.P$A LED20.59.P$A LED20.123.P$A LED21.59.P$A
N$X.60: LED9.60.P$A LED10.60.P$A LED11.60.P$A LED11.124.P$A LED12.60.P$A LED12.124.P$A LED13.60.P$A LED13.124.P$A LED14.60.P$A LED14.124.P$A LED15.60.P$A LED15.124.P$A LED16.60.P$A LED16.124.P$A LED17.60.P$A LED17.124.P$A LED18.60.P$A LED18.124.P$A LED19.60.P$A LED19.124.P$A LED20.60.P$A LED20.124.P$A LED21.60.P$A
N$X.61: LED9.61.P$A LED10.61.P$A LED11.61.P$A LED11.125.P$A LED12.61.P$A LED12.125.P$A LED13.61.P$A LED13.125.P$A LED14.61.P$A LED14.125.P$A LED15.61.P$A LED15.125.P$A LED16.61.P$A LED16.125.P$A LED17.61.P$A LED17.125.P$A LED18.61.P$A LED18.125.P$A LED19.61.P$A LED19.125.P$A LED20.61.P$A LED20.125.P$A LED21.61.P$A
N$X.62: LED6.62.P$A LED7.62.P$A LED8.62.P$A LED9.62.P$A LED10.62.P$A LED11.62.P$A LED11.126.P$A LED12.62.P$A LED12.126.P$A LED13.62.P$A LED13.126.P$A LED14.62.P$A LED14.126.P$A LED15.62.P$A LED15.126.P$A LED16.62.P$A LED16.126.P$A LED17.62.P$A LED17.126.P$A LED18.62.P$A LED18.126.P$A LED19.62.P$A LED19.126.P$A LED20.62.P$A LED20.126.P$A LED21.62.P$A
N$X.63: LED1.63.P$A LED2.63.P$A LED3.63.P$A LED4.63.P$A LED5.63.P$A LED6.63.P$A LED7.63.P$A LED8.63.P$A LED9.63.P$A LED10.63.P$A LED11.63.P$A LED11.127.P$A LED12.63.P$A LED12.127.P$A LED13.63.P$A LED13.127.P$A LED14.63.P$A LED14.127.P$A LED15.63.P$A LED16.63.P$A LED17.63.P$A LED18.63.P$A LED19.63.P$A LED20.63.P$A LED21.63.P$A X63.P$
N$X.120: LED2.68.P$A
N$X.620: LED14.131.P$A
N$X.767: LED14.96.P$A
N$X.768: LED1.36.P$A LED2.36.P$A
N$X.769: LED2.72.P$A
N$X.771: LED2.73.P$A
N$X.772: LED14.98.P$A
N$X.773: LED1.64.P$A LED2.64.P$A
N$X.777: LED14.128.P$A
N$X.784: LED1.65.P$A LED2.65.P$A
N$X.785: LED2.69.P$A
N$X.789: LED14.129.P$A
N$X.790: LED1.66.P$A LED2.66.P$A
N$X.797: LED2.67.P$A
N$X.799: LED14.130.P$A
N$X.802: LED2.74.P$A
N$X.804: LED14.132.P$A
N$X.806: LED2.70.P$A
N$X.808: LED14.133.P$A
N$X.816: LED2.71.P$A
N$X.820: LED2.75.P$A
N$X.822: LED2.76.P$A
N$X.824: LED2.77.P$A
N$X.826: LED2.78.P$A
N$X.828: LED2.79.P$A
N$X.830: LED2.80.P$A
N$X.832: LED2.81.P$A
N$X.834: LED2.82.P$A
N$Y.0: LED0.0.P$K LED0.1.P$K LED0.2.P$K LED0.3.P$K LED0.4.P$K Y.0.P$
N$Y.1: LED1.2.P$K LED1.3.P$K LED1.4.P$K LED1.5.P$K LED1.6.P$K LED1.7.P$K LED1.8.P$K LED1.9.P$K LED1.10.P$K LED1.11.P$K LED1.12.P$K LED1.13.P$K LED1.14.P$K LED1.15.P$K LED1.16.P$K LED1.17.P$K LED1.18.P$K LED1.19.P$K LED1.20.P$K LED1.21.P$K
N$Y.2: LED2.2.P$K LED2.3.P$K LED2.4.P$K LED2.5.P$K LED2.6.P$K LED2.7.P$K LED2.8.P$K LED2.9.P$K LED2.10.P$K LED2.11.P$K LED2.12.P$K LED2.13.P$K LED2.14.P$K LED2.15.P$K LED2.16.P$K LED2.17.P$K LED2.18.P$K LED2.19.P$K LED2.20.P$K LED2.21.P$K LED2.22.P$K
N$Y.3: LED3.0.P$K LED3.1.P$K LED3.2.P$K LED3.3.P$K LED3.4.P$K LED3.5.P$K LED3.6.P$K LED3.7.P$K LED3.8.P$K LED3.9.P$K LED3.10.P$K LED3.11.P$K LED3.12.P$K LED3.13.P$K LED3.14.P$K LED3.15.P$K LED3.16.P$K LED3.17.P$K LED3.18.P$K LED3.19.P$K LED3.20.P$K LED3.21.P$K LED3.22.P$K LED3.23.P$K LED3.24.P$K Y.3.P$
N$Y.4: LED4.2.P$K LED4.3.P$K LED4.4.P$K LED4.5.P$K LED4.6.P$K LED4.7.P$K LED4.8.P$K LED4.9.P$K LED4.10.P$K LED4.11.P$K LED4.12.P$K LED4.13.P$K LED4.14.P$K LED4.15.P$K LED4.16.P$K LED4.17.P$K
N$Y.5: LED5.5.P$K LED5.6.P$K LED5.7.P$K LED5.8.P$K LED5.9.P$K LED5.10.P$K LED5.11.P$K LED5.12.P$K LED5.13.P$K LED5.14.P$K LED5.15.P$K LED5.16.P$K LED5.17.P$K LED5.18.P$K LED5.19.P$K LED5.20.P$K LED5.21.P$K LED5.22.P$K LED5.23.P$K LED5.24.P$K LED5.25.P$K
N$Y.6: LED6.13.P$K LED6.14.P$K LED6.15.P$K LED6.16.P$K LED6.17.P$K LED6.18.P$K LED6.19.P$K LED6.20.P$K LED6.21.P$K LED6.22.P$K LED6.23.P$K LED6.24.P$K LED6.25.P$K LED6.26.P$K LED6.27.P$K LED6.28.P$K LED6.29.P$K
N$Y.7: LED7.0.P$K LED7.1.P$K LED7.2.P$K LED7.3.P$K LED7.4.P$K LED7.5.P$K LED7.6.P$K LED7.7.P$K LED7.8.P$K LED7.9.P$K LED7.10.P$K LED7.11.P$K LED7.12.P$K LED7.13.P$K LED7.14.P$K LED7.15.P$K LED7.16.P$K LED7.17.P$K LED7.18.P$K LED7.19.P$K LED7.20.P$K LED7.21.P$K LED7.22.P$K LED7.23.P$K LED7.24.P$K LED7.25.P$K LED7.26.P$K LED7.27.P$K LED7.28.P$K LED7.29.P$K LED7.30.P$K Y.7.P$
N$Y.8: LED8.28.P$K LED8.29.P$K LED8.30.P$K LED8.31.P$K LED8.33.P$K LED8.34.P$K LED8.35.P$K LED8.36.P$K LED8.37.P$K LED8.38.P$K LED8.39.P$K LED8.40.P$K LED8.41.P$K LED8.42.P$K LED8.43.P$K LED8.44.P$K LED8.45.P$K LED8.46.P$K LED8.47.P$K LED8.48.P$K
N$Y.9: LED9.35.P$K LED9.36.P$K LED9.37.P$K LED9.38.P$K LED9.39.P$K LED9.40.P$K LED9.41.P$K LED9.42.P$K LED9.43.P$K LED9.44.P$K LED9.45.P$K LED9.46.P$K LED9.47.P$K
N$Y.10: LED10.38.P$K LED10.39.P$K LED10.40.P$K LED10.41.P$K LED10.42.P$K LED10.43.P$K LED10.44.P$K LED10.45.P$K LED10.46.P$K LED10.47.P$K LED10.48.P$K LED10.49.P$K LED10.50.P$K LED10.51.P$K LED10.52.P$K LED10.53.P$K LED10.54.P$K LED10.55.P$K LED10.56.P$K LED10.57.P$K LED10.58.P$K LED10.59.P$K LED10.60.P$K LED10.61.P$K LED10.62.P$K LED10.63.P$K
N$Y.11: LED11.0.P$K LED11.1.P$K LED11.2.P$K LED11.3.P$K LED11.4.P$K LED11.5.P$K LED11.6.P$K LED11.7.P$K LED11.8.P$K LED11.9.P$K LED11.10.P$K LED11.11.P$K LED11.12.P$K LED11.13.P$K LED11.14.P$K LED11.15.P$K LED11.16.P$K LED11.17.P$K LED11.18.P$K LED11.19.P$K LED11.20.P$K LED11.21.P$K LED11.22.P$K LED11.23.P$K LED11.24.P$K LED11.25.P$K LED11.26.P$K LED11.27.P$K LED11.28.P$K LED11.29.P$K LED11.30.P$K LED11.31.P$K LED11.33.P$K LED11.34.P$K LED11.35.P$K LED11.36.P$K LED11.37.P$K LED11.38.P$K LED11.39.P$K LED11.40.P$K LED11.41.P$K LED11.42.P$K LED11.43.P$K LED11.44.P$K LED11.45.P$K LED11.46.P$K LED11.47.P$K LED11.48.P$K LED11.49.P$K LED11.50.P$K LED11.51.P$K LED11.52.P$K LED11.53.P$K LED11.54.P$K LED11.55.P$K LED11.56.P$K LED11.57.P$K LED11.58.P$K LED11.59.P$K LED11.60.P$K LED11.61.P$K LED11.62.P$K LED11.63.P$K Y.11.P$
N$Y.12: LED12.0.P$K LED12.1.P$K LED12.2.P$K LED12.3.P$K LED12.4.P$K LED12.5.P$K LED12.6.P$K LED12.7.P$K LED12.8.P$K LED12.9.P$K LED12.10.P$K LED12.11.P$K LED12.12.P$K LED12.13.P$K LED12.14.P$K LED12.15.P$K LED12.16.P$K LED12.17.P$K LED12.18.P$K LED12.19.P$K LED12.20.P$K LED12.21.P$K LED12.22.P$K LED12.23.P$K LED12.24.P$K LED12.25.P$K LED12.26.P$K LED12.27.P$K LED12.28.P$K LED12.29.P$K LED12.30.P$K LED12.31.P$K LED12.33.P$K LED12.34.P$K LED12.35.P$K LED12.36.P$K LED12.37.P$K LED12.38.P$K LED12.39.P$K LED12.40.P$K LED12.41.P$K LED12.42.P$K LED12.43.P$K Y.12.P$
N$Y.13: LED13.0.P$K LED13.1.P$K LED13.2.P$K LED13.3.P$K LED13.4.P$K LED13.5.P$K LED13.6.P$K LED13.7.P$K LED13.8.P$K LED13.9.P$K LED13.10.P$K LED13.11.P$K LED13.12.P$K LED13.13.P$K LED13.14.P$K LED13.15.P$K LED13.16.P$K LED13.17.P$K LED13.18.P$K LED13.19.P$K LED13.20.P$K LED13.21.P$K LED13.22.P$K LED13.23.P$K LED13.24.P$K LED13.25.P$K LED13.26.P$K LED13.27.P$K LED13.28.P$K LED13.29.P$K LED13.30.P$K LED13.31.P$K LED13.32.P$K LED13.34.P$K LED13.35.P$K LED13.36.P$K LED13.37.P$K LED13.38.P$K LED13.39.P$K LED13.40.P$K LED13.41.P$K LED13.42.P$K LED13.43.P$K LED13.44.P$K LED13.45.P$K LED13.46.P$K LED13.47.P$K LED13.48.P$K LED13.49.P$K LED13.50.P$K LED13.51.P$K LED13.52.P$K LED13.53.P$K LED13.54.P$K LED13.55.P$K LED13.56.P$K LED13.57.P$K LED13.58.P$K LED13.59.P$K LED13.60.P$K LED13.61.P$K LED13.62.P$K LED13.63.P$K Y.13.P$
N$Y.14: LED14.0.P$K LED14.1.P$K LED14.2.P$K LED14.3.P$K LED14.4.P$K LED14.5.P$K LED14.6.P$K LED14.7.P$K LED14.8.P$K LED14.9.P$K LED14.10.P$K LED14.11.P$K LED14.12.P$K LED14.13.P$K LED14.14.P$K LED14.15.P$K LED14.16.P$K LED14.17.P$K LED14.18.P$K LED14.19.P$K LED14.20.P$K LED14.21.P$K LED14.22.P$K LED14.23.P$K LED14.24.P$K LED14.25.P$K LED14.26.P$K LED14.27.P$K LED14.28.P$K LED14.29.P$K LED14.30.P$K LED14.31.P$K LED14.32.P$K LED14.33.P$K LED14.34.P$K LED14.35.P$K LED14.36.P$K LED14.37.P$K LED14.38.P$K LED14.39.P$K LED14.40.P$K LED14.41.P$K LED14.42.P$K LED14.43.P$K LED14.44.P$K LED14.45.P$K LED14.46.P$K LED14.47.P$K LED14.48.P$K LED14.49.P$K LED14.50.P$K LED14.51.P$K LED14.52.P$K LED14.53.P$K LED14.54.P$K LED14.55.P$K LED14.56.P$K LED14.57.P$K LED14.58.P$K LED14.59.P$K LED14.60.P$K LED14.61.P$K LED14.62.P$K LED14.63.P$K Y.14.P$
N$Y.15: LED15.0.P$K LED15.1.P$K LED15.2.P$K LED15.3.P$K LED15.4.P$K LED15.5.P$K LED15.6.P$K LED15.7.P$K LED15.8.P$K LED15.9.P$K LED15.10.P$K LED15.11.P$K LED15.12.P$K LED15.13.P$K LED15.14.P$K LED15.15.P$K LED15.16.P$K LED15.17.P$K LED15.18.P$K LED15.19.P$K LED15.20.P$K LED15.21.P$K LED15.22.P$K LED15.23.P$K LED15.24.P$K LED15.25.P$K LED15.26.P$K LED15.27.P$K LED15.28.P$K LED15.29.P$K LED15.30.P$K LED15.31.P$K LED15.32.P$K LED15.34.P$K LED15.35.P$K LED15.36.P$K LED15.37.P$K LED15.38.P$K LED15.39.P$K LED15.40.P$K LED15.41.P$K LED15.42.P$K LED15.43.P$K LED15.44.P$K LED15.45.P$K LED15.46.P$K LED15.47.P$K LED15.48.P$K Y.15.P$
N$Y.16: LED16.0.P$K LED16.1.P$K LED16.2.P$K LED16.3.P$K LED16.4.P$K LED16.5.P$K LED16.6.P$K LED16.7.P$K LED16.8.P$K LED16.9.P$K LED16.10.P$K LED16.11.P$K LED16.12.P$K LED16.13.P$K LED16.14.P$K LED16.15.P$K LED16.16.P$K LED16.17.P$K LED16.18.P$K LED16.19.P$K LED16.20.P$K LED16.21.P$K LED16.22.P$K LED16.23.P$K LED16.24.P$K LED16.25.P$K LED16.26.P$K LED16.27.P$K LED16.28.P$K LED16.29.P$K LED16.30.P$K LED16.31.P$K LED16.33.P$K LED16.34.P$K LED16.35.P$K LED16.36.P$K LED16.37.P$K LED16.38.P$K LED16.39.P$K LED16.40.P$K LED16.41.P$K LED16.42.P$K LED16.43.P$K LED16.44.P$K LED16.45.P$K LED16.46.P$K LED16.47.P$K LED16.48.P$K LED16.49.P$K LED16.50.P$K LED16.51.P$K LED16.52.P$K LED16.53.P$K LED16.54.P$K LED16.55.P$K LED16.56.P$K LED16.57.P$K LED16.58.P$K LED16.59.P$K LED16.60.P$K LED16.61.P$K LED16.62.P$K LED16.63.P$K Y.16.P$
N$Y.17: LED17.0.P$K LED17.1.P$K LED17.2.P$K LED17.3.P$K LED17.4.P$K LED17.5.P$K LED17.6.P$K LED17.7.P$K LED17.8.P$K LED17.9.P$K LED17.10.P$K LED17.11.P$K LED17.12.P$K LED17.13.P$K LED17.14.P$K LED17.15.P$K LED17.16.P$K LED17.17.P$K LED17.18.P$K LED17.19.P$K LED17.20.P$K LED17.21.P$K LED17.22.P$K LED17.23.P$K LED17.24.P$K LED17.25.P$K LED17.26.P$K LED17.27.P$K LED17.28.P$K LED17.29.P$K LED17.30.P$K LED17.31.P$K LED17.33.P$K LED17.34.P$K LED17.35.P$K LED17.36.P$K LED17.37.P$K LED17.38.P$K LED17.39.P$K LED17.40.P$K LED17.41.P$K LED17.42.P$K LED17.43.P$K LED17.44.P$K LED17.45.P$K LED17.46.P$K Y.17.P$
N$Y.18: LED18.0.P$K LED18.1.P$K LED18.2.P$K LED18.3.P$K LED18.4.P$K LED18.5.P$K LED18.6.P$K LED18.7.P$K LED18.8.P$K LED18.9.P$K LED18.10.P$K LED18.11.P$K LED18.12.P$K LED18.13.P$K LED18.14.P$K LED18.15.P$K LED18.16.P$K LED18.17.P$K LED18.18.P$K LED18.19.P$K LED18.20.P$K LED18.21.P$K LED18.22.P$K LED18.23.P$K LED18.24.P$K LED18.25.P$K LED18.26.P$K LED18.27.P$K LED18.28.P$K LED18.29.P$K LED18.30.P$K LED18.31.P$K LED18.33.P$K LED18.34.P$K LED18.35.P$K LED18.36.P$K LED18.37.P$K LED18.38.P$K LED18.39.P$K LED18.40.P$K LED18.41.P$K LED18.42.P$K LED18.43.P$K LED18.44.P$K LED18.45.P$K LED18.46.P$K LED18.47.P$K LED18.48.P$K LED18.49.P$K LED18.50.P$K LED18.51.P$K LED18.52.P$K LED18.53.P$K LED18.54.P$K LED18.55.P$K LED18.56.P$K LED18.57.P$K LED18.58.P$K LED18.59.P$K LED18.60.P$K LED18.61.P$K LED18.62.P$K LED18.63.P$K Y.18.P$
N$Y.19: LED19.0.P$K LED19.1.P$K LED19.2.P$K LED19.3.P$K LED19.4.P$K LED19.5.P$K LED19.6.P$K LED19.7.P$K LED19.8.P$K LED19.9.P$K LED19.10.P$K LED19.11.P$K LED19.12.P$K LED19.13.P$K LED19.14.P$K LED19.15.P$K LED19.16.P$K LED19.17.P$K LED19.18.P$K LED19.19.P$K LED19.20.P$K LED19.21.P$K LED19.22.P$K LED19.23.P$K LED19.24.P$K LED19.25.P$K LED19.26.P$K LED19.27.P$K LED19.28.P$K LED19.29.P$K LED19.30.P$K LED19.31.P$K LED19.33.P$K LED19.34.P$K LED19.35.P$K LED19.36.P$K LED19.37.P$K LED19.38.P$K LED19.39.P$K LED19.40.P$K LED19.41.P$K LED19.42.P$K LED19.43.P$K LED19.44.P$K LED19.45.P$K LED19.46.P$K LED19.47.P$K LED19.48.P$K LED19.49.P$K LED19.50.P$K LED19.51.P$K LED19.52.P$K LED19.53.P$K LED19.54.P$K LED19.55.P$K LED19.56.P$K LED19.57.P$K LED19.58.P$K LED19.59.P$K LED19.60.P$K LED19.61.P$K LED19.62.P$K LED19.63.P$K Y.19.P$
N$Y.20: LED20.0.P$K LED20.1.P$K LED20.2.P$K LED20.3.P$K LED20.4.P$K LED20.5.P$K LED20.6.P$K LED20.7.P$K LED20.8.P$K LED20.9.P$K LED20.10.P$K LED20.11.P$K LED20.12.P$K LED20.13.P$K LED20.14.P$K LED20.15.P$K LED20.16.P$K LED20.17.P$K LED20.18.P$K LED20.19.P$K LED20.20.P$K LED20.21.P$K LED20.22.P$K LED20.23.P$K LED20.24.P$K LED20.25.P$K LED20.26.P$K LED20.27.P$K LED20.28.P$K LED20.29.P$K LED20.30.P$K LED20.31.P$K LED20.33.P$K LED20.34.P$K LED20.35.P$K LED20.36.P$K LED20.37.P$K LED20.38.P$K LED20.39.P$K LED20.40.P$K LED20.41.P$K LED20.42.P$K LED20.43.P$K LED20.44.P$K LED20.45.P$K LED20.46.P$K LED20.47.P$K LED20.48.P$K LED20.49.P$K LED20.50.P$K LED20.51.P$K LED20.52.P$K LED20.53.P$K LED20.54.P$K LED20.55.P$K LED20.56.P$K LED20.57.P$K LED20.58.P$K LED20.59.P$K LED20.60.P$K LED20.61.P$K LED20.62.P$K LED20.63.P$K Y.20.P$
N$Y.21: LED21.0.P$K LED21.1.P$K LED21.2.P$K LED21.3.P$K LED21.4.P$K LED21.5.P$K LED21.6.P$K LED21.7.P$K LED21.8.P$K LED21.9.P$K LED21.10.P$K LED21.11.P$K LED21.12.P$K LED21.13.P$K LED21.14.P$K LED21.15.P$K LED21.16.P$K LED21.17.P$K LED21.18.P$K LED21.19.P$K LED21.20.P$K LED21.21.P$K LED21.22.P$K LED21.23.P$K LED21.24.P$K LED21.25.P$K LED21.26.P$K LED21.27.P$K LED21.28.P$K LED21.29.P$K LED21.30.P$K LED21.31.P$K LED21.33.P$K LED21.34.P$K LED21.35.P$K LED21.36.P$K LED21.37.P$K LED21.38.P$K LED21.39.P$K LED21.40.P$K LED21.41.P$K LED21.42.P$K LED21.43.P$K LED21.44.P$K LED21.45.P$K LED21.46.P$K LED21.47.P$K LED21.48.P$K LED21.49.P$K LED21.50.P$K LED21.51.P$K LED21.52.P$K LED21.53.P$K LED21.54.P$K LED21.55.P$K LED21.56.P$K LED21.57.P$K LED21.58.P$K LED21.59.P$K LED21.60.P$K LED21.61.P$K LED21.62.P$K LED21.63.P$K Y.21.P$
